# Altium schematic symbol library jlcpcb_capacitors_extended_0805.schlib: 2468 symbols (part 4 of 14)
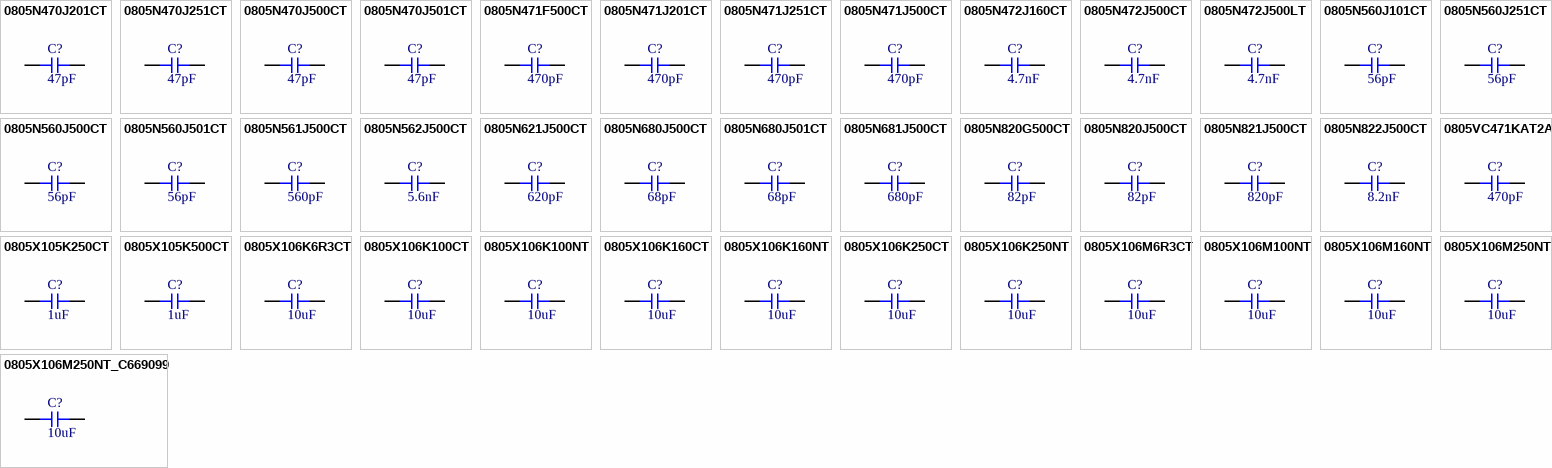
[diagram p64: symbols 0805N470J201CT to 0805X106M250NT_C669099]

## 0805N621J500CT
designator C?  Capacitance: 620pF  (hidden comment: *)
Capacitor, Ceramic (MLCC), 620pF, ±5%, 50V, NP0, ±5%, SMD 0805; Manufacturer: Walsin Tech Corp; Manufacturer Part Number: 0805N621J500CT
footprint CAP-0805 (0805 (2012M) Capacitor)
pins: 1, 2

## 0805N680J500CT
designator C?  Capacitance: 68pF  (hidden comment: *)
Capacitor, Ceramic (MLCC), 68pF, ±5%, 50V, NP0, ±5%, SMD 0805; Manufacturer: Walsin Tech Corp; Manufacturer Part Number: 0805N680J500CT
footprint CAP-0805 (0805 (2012M) Capacitor)
pins: 1, 2

## 0805N680J501CT
designator C?  Capacitance: 68pF  (hidden comment: *)
Capacitor, Ceramic (MLCC), 68pF, ±5%, 500V, NP0, ±5%, SMD 0805; Manufacturer: Walsin Tech Corp; Manufacturer Part Number: 0805N680J501CT
footprint CAP-0805 (0805 (2012M) Capacitor)
pins: 1, 2

## 0805N681J500CT
designator C?  Capacitance: 680pF  (hidden comment: *)
Capacitor, Ceramic (MLCC), 680pF, ±5%, 50V, NP0, ±5%, SMD 0805; Manufacturer: Walsin Tech Corp; Manufacturer Part Number: 0805N681J500CT
footprint CAP-0805 (0805 (2012M) Capacitor)
pins: 1, 2

## 0805N820G500CT
designator C?  Capacitance: 82pF  (hidden comment: *)
Capacitor, Ceramic (MLCC), 82pF, ±2%, 50V, NP0, ±2%, SMD 0805; Manufacturer: Walsin Tech Corp; Manufacturer Part Number: 0805N820G500CT
footprint CAP-0805 (0805 (2012M) Capacitor)
pins: 1, 2

## 0805N820J500CT
designator C?  Capacitance: 82pF  (hidden comment: *)
Capacitor, Ceramic (MLCC), 82pF, ±5%, 50V, NP0, ±5%, SMD 0805; Manufacturer: Walsin Tech Corp; Manufacturer Part Number: 0805N820J500CT
footprint CAP-0805 (0805 (2012M) Capacitor)
pins: 1, 2

## 0805N821J500CT
designator C?  Capacitance: 820pF  (hidden comment: *)
Capacitor, Ceramic (MLCC), 820pF, ±5%, 50V, NP0, ±5%, SMD 0805; Manufacturer: Walsin Tech Corp; Manufacturer Part Number: 0805N821J500CT
footprint CAP-0805 (0805 (2012M) Capacitor)
pins: 1, 2

## 0805N822J500CT
designator C?  Capacitance: 8.2nF  (hidden comment: *)
Capacitor, Ceramic (MLCC), 8.2nF, ±5%, 50V, NP0, ±5%, SMD 0805; Manufacturer: Walsin Tech Corp; Manufacturer Part Number: 0805N822J500CT
footprint CAP-0805 (0805 (2012M) Capacitor)
pins: 1, 2

## 0805VC471KAT2A
designator C?  Capacitance: 470pF  (hidden comment: *)
Capacitor, Ceramic (MLCC), 470pF, ±10%, 250V, X7R, ±10%, SMD 0805; Manufacturer: AVX; Manufacturer Part Number: 0805VC471KAT2A
footprint CAP-0805 (0805 (2012M) Capacitor)
pins: 1, 2

## 0805X105K250CT
designator C?  Capacitance: 1uF  (hidden comment: *)
Capacitor, Ceramic (MLCC), 1uF, ±10%, 25V, X5R, ±10%, SMD 0805; Manufacturer: Walsin Tech Corp; Manufacturer Part Number: 0805X105K250CT
footprint CAP-0805 (0805 (2012M) Capacitor)
pins: 1, 2

## 0805X105K500CT
designator C?  Capacitance: 1uF  (hidden comment: *)
Capacitor, Ceramic (MLCC), 1uF, ±10%, 50V, X5R, ±10%, SMD 0805; Manufacturer: Walsin Tech Corp; Manufacturer Part Number: 0805X105K500CT
footprint CAP-0805 (0805 (2012M) Capacitor)
pins: 1, 2

## 0805X106K6R3CT
designator C?  Capacitance: 10uF  (hidden comment: *)
Capacitor, Ceramic (MLCC), 10uF, ±10%, 6.3V, X5R, ±10%, SMD 0805; Manufacturer: Walsin Tech Corp; Manufacturer Part Number: 0805X106K6R3CT
footprint CAP-0805 (0805 (2012M) Capacitor)
pins: 1, 2

## 0805X106K100CT
designator C?  Capacitance: 10uF  (hidden comment: *)
Capacitor, Ceramic (MLCC), 10uF, ±10%, 10V, X5R, ±10%, SMD 0805; Manufacturer: Walsin Tech Corp; Manufacturer Part Number: 0805X106K100CT
footprint CAP-0805 (0805 (2012M) Capacitor)
pins: 1, 2

## 0805X106K100NT
designator C?  Capacitance: 10uF  (hidden comment: *)
Capacitor, Ceramic (MLCC), 10uF, ±10%, 10V, X5R, ±10%, SMD 0805; Manufacturer: FH(Guangdong Fenghua Advanced Tech); Manufacturer Part Number: 0805X106K100NT
footprint CAP-0805 (0805 (2012M) Capacitor)
pins: 1, 2

## 0805X106K160CT
designator C?  Capacitance: 10uF  (hidden comment: *)
Capacitor, Ceramic (MLCC), 10uF, ±10%, 16V, X5R, ±10%, SMD 0805; Manufacturer: Walsin Tech Corp; Manufacturer Part Number: 0805X106K160CT
footprint CAP-0805 (0805 (2012M) Capacitor)
pins: 1, 2

## 0805X106K160NT
designator C?  Capacitance: 10uF  (hidden comment: *)
Capacitor, Ceramic (MLCC), 10uF, ±10%, 16V, X5R, ±10%, SMD 0805; Manufacturer: FH(Guangdong Fenghua Advanced Tech); Manufacturer Part Number: 0805X106K160NT
footprint CAP-0805 (0805 (2012M) Capacitor)
pins: 1, 2

## 0805X106K250CT
designator C?  Capacitance: 10uF  (hidden comment: *)
Capacitor, Ceramic (MLCC), 10uF, ±10%, 25V, X5R, ±10%, SMD 0805; Manufacturer: Walsin Tech Corp; Manufacturer Part Number: 0805X106K250CT
footprint CAP-0805 (0805 (2012M) Capacitor)
pins: 1, 2

## 0805X106K250NT
designator C?  Capacitance: 10uF  (hidden comment: *)
Capacitor, Ceramic (MLCC), 10uF, ±10%, 25V, X5R, ±10%, SMD 0805; Manufacturer: FH(Guangdong Fenghua Advanced Tech); Manufacturer Part Number: 0805X106K250NT
footprint CAP-0805 (0805 (2012M) Capacitor)
pins: 1, 2

## 0805X106M6R3CT
designator C?  Capacitance: 10uF  (hidden comment: *)
Capacitor, Ceramic (MLCC), 10uF, ±20%, 6.3V, X5R, ±20%, SMD 0805; Manufacturer: Walsin Tech Corp; Manufacturer Part Number: 0805X106M6R3CT
footprint CAP-0805 (0805 (2012M) Capacitor)
pins: 1, 2

## 0805X106M100NT
designator C?  Capacitance: 10uF  (hidden comment: *)
Capacitor, Ceramic (MLCC), 10uF, ±20%, 10V, X5R, ±20%, SMD 0805; Manufacturer: FH(Guangdong Fenghua Advanced Tech); Manufacturer Part Number: 0805X106M100NT
footprint CAP-0805 (0805 (2012M) Capacitor)
pins: 1, 2

## 0805X106M160NT
designator C?  Capacitance: 10uF  (hidden comment: *)
Capacitor, Ceramic (MLCC), 10uF, ±20%, 16V, X5R, ±20%, SMD 0805; Manufacturer: FH(Guangdong Fenghua Advanced Tech); Manufacturer Part Number: 0805X106M160NT
footprint CAP-0805 (0805 (2012M) Capacitor)
pins: 1, 2

## 0805X106M250NT
designator C?  Capacitance: 10uF  (hidden comment: *)
Capacitor, Ceramic (MLCC), 10uF, ±20%, 25V, X5R, ±20%, SMD 0805; Manufacturer: FH(Guangdong Fenghua Advanced Tech); Manufacturer Part Number: 0805X106M250NT
footprint CAP-0805 (0805 (2012M) Capacitor)
pins: 1, 2

## 0805X106M250NT_C669099
designator C?  Capacitance: 10uF  (hidden comment: *)
Capacitor, Ceramic (MLCC), 10uF, ±20%, 25V, X5R, ±20%, SMD 0805; Manufacturer: FH(Guangdong Fenghua Advanced Tech); Manufacturer Part Number: 0805X106M250NT
footprint CAP-0805 (0805 (2012M) Capacitor)
pins: 1, 2

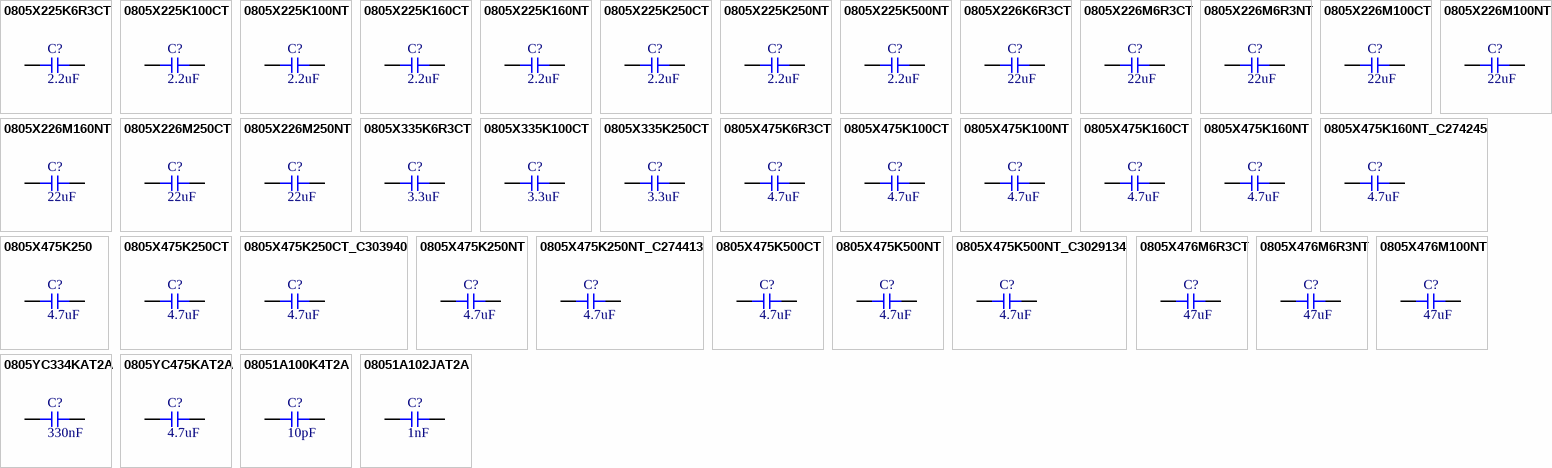
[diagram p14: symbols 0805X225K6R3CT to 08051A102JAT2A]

## 0805X225K6R3CT
designator C?  Capacitance: 2.2uF  (hidden comment: *)
Capacitor, Ceramic (MLCC), 2.2uF, ±10%, 6.3V, X5R, ±10%, SMD 0805; Manufacturer: Walsin Tech Corp; Manufacturer Part Number: 0805X225K6R3CT
footprint CAP-0805 (0805 (2012M) Capacitor)
pins: 1, 2

## 0805X225K100CT
designator C?  Capacitance: 2.2uF  (hidden comment: *)
Capacitor, Ceramic (MLCC), 2.2uF, ±10%, 10V, X5R, ±10%, SMD 0805; Manufacturer: Walsin Tech Corp; Manufacturer Part Number: 0805X225K100CT
footprint CAP-0805 (0805 (2012M) Capacitor)
pins: 1, 2

## 0805X225K100NT
designator C?  Capacitance: 2.2uF  (hidden comment: *)
Capacitor, Ceramic (MLCC), 2.2uF, ±10%, 10V, ±10%, SMD 0805; Manufacturer: FH(Guangdong Fenghua Advanced Tech); Manufacturer Part Number: 0805X225K100NT
footprint CAP-0805 (0805 (2012M) Capacitor)
pins: 1, 2

## 0805X225K160CT
designator C?  Capacitance: 2.2uF  (hidden comment: *)
Capacitor, Ceramic (MLCC), 2.2uF, ±10%, 16V, X5R, ±10%, SMD 0805; Manufacturer: Walsin Tech Corp; Manufacturer Part Number: 0805X225K160CT
footprint CAP-0805 (0805 (2012M) Capacitor)
pins: 1, 2

## 0805X225K160NT
designator C?  Capacitance: 2.2uF  (hidden comment: *)
Capacitor, Ceramic (MLCC), 2.2uF, ±10%, 16V, X5R, ±10%, SMD 0805; Manufacturer: FH(Guangdong Fenghua Advanced Tech); Manufacturer Part Number: 0805X225K160NT
footprint CAP-0805 (0805 (2012M) Capacitor)
pins: 1, 2

## 0805X225K250CT
designator C?  Capacitance: 2.2uF  (hidden comment: *)
Capacitor, Ceramic (MLCC), 2.2uF, ±10%, 25V, X5R, ±10%, SMD 0805; Manufacturer: Walsin Tech Corp; Manufacturer Part Number: 0805X225K250CT
footprint CAP-0805 (0805 (2012M) Capacitor)
pins: 1, 2

## 0805X225K250NT
designator C?  Capacitance: 2.2uF  (hidden comment: *)
Capacitor, Ceramic (MLCC), 2.2uF, ±10%, 25V, X5R, ±10%, SMD 0805; Manufacturer: FH(Guangdong Fenghua Advanced Tech); Manufacturer Part Number: 0805X225K250NT
footprint CAP-0805 (0805 (2012M) Capacitor)
pins: 1, 2

## 0805X225K500NT
designator C?  Capacitance: 2.2uF  (hidden comment: *)
Capacitor, Ceramic (MLCC), 2.2uF, ±10%, 50V, X5R, ±10%, SMD 0805; Manufacturer: FH(Guangdong Fenghua Advanced Tech); Manufacturer Part Number: 0805X225K500NT
footprint CAP-0805 (0805 (2012M) Capacitor)
pins: 1, 2

## 0805X226K6R3CT
designator C?  Capacitance: 22uF  (hidden comment: *)
Capacitor, Ceramic (MLCC), 22uF, ±10%, 6.3V, X5R, ±10%, SMD 0805; Manufacturer: Walsin Tech Corp; Manufacturer Part Number: 0805X226K6R3CT
footprint CAP-0805 (0805 (2012M) Capacitor)
pins: 1, 2

## 0805X226M6R3CT
designator C?  Capacitance: 22uF  (hidden comment: *)
Capacitor, Ceramic (MLCC), 22uF, ±20%, 6.3V, X5R, ±20%, SMD 0805; Manufacturer: Walsin Tech Corp; Manufacturer Part Number: 0805X226M6R3CT
footprint CAP-0805 (0805 (2012M) Capacitor)
pins: 1, 2

## 0805X226M6R3NT
designator C?  Capacitance: 22uF  (hidden comment: *)
Capacitor, Ceramic (MLCC), 22uF, ±20%, 6.3V, X5R, ±20%, SMD 0805; Manufacturer: FH(Guangdong Fenghua Advanced Tech); Manufacturer Part Number: 0805X226M6R3NT
footprint CAP-0805 (0805 (2012M) Capacitor)
pins: 1, 2

## 0805X226M100CT
designator C?  Capacitance: 22uF  (hidden comment: *)
Capacitor, Ceramic (MLCC), 22uF, ±20%, 10V, X5R, ±20%, SMD 0805; Manufacturer: Walsin Tech Corp; Manufacturer Part Number: 0805X226M100CT
footprint CAP-0805 (0805 (2012M) Capacitor)
pins: 1, 2

## 0805X226M100NT
designator C?  Capacitance: 22uF  (hidden comment: *)
Capacitor, Ceramic (MLCC), 22uF, ±20%, 10V, X5R, ±20%, SMD 0805; Manufacturer: FH(Guangdong Fenghua Advanced Tech); Manufacturer Part Number: 0805X226M100NT
footprint CAP-0805 (0805 (2012M) Capacitor)
pins: 1, 2

## 0805X226M160NT
designator C?  Capacitance: 22uF  (hidden comment: *)
Capacitor, Ceramic (MLCC), 22uF, ±20%, 16V, X5R, ±20%, SMD 0805; Manufacturer: FH(Guangdong Fenghua Advanced Tech); Manufacturer Part Number: 0805X226M160NT
footprint CAP-0805 (0805 (2012M) Capacitor)
pins: 1, 2

## 0805X226M250CT
designator C?  Capacitance: 22uF  (hidden comment: *)
Capacitor, Ceramic (MLCC), 22uF, ±20%, 25V, X5R, ±20%, SMD 0805; Manufacturer: Walsin Tech Corp; Manufacturer Part Number: 0805X226M250CT
footprint CAP-0805 (0805 (2012M) Capacitor)
pins: 1, 2

## 0805X226M250NT
designator C?  Capacitance: 22uF  (hidden comment: *)
Capacitor, Ceramic (MLCC), 22uF, ±20%, 25V, X5R, ±20%, SMD 0805; Manufacturer: FH(Guangdong Fenghua Advanced Tech); Manufacturer Part Number: 0805X226M250NT
footprint CAP-0805 (0805 (2012M) Capacitor)
pins: 1, 2

## 0805X335K6R3CT
designator C?  Capacitance: 3.3uF  (hidden comment: *)
Capacitor, Ceramic (MLCC), 3.3uF, ±10%, 6.3V, X5R, ±10%, SMD 0805; Manufacturer: Walsin Tech Corp; Manufacturer Part Number: 0805X335K6R3CT
footprint CAP-0805 (0805 (2012M) Capacitor)
pins: 1, 2

## 0805X335K100CT
designator C?  Capacitance: 3.3uF  (hidden comment: *)
Capacitor, Ceramic (MLCC), 3.3uF, ±10%, 10V, X5R, ±10%, SMD 0805; Manufacturer: Walsin Tech Corp; Manufacturer Part Number: 0805X335K100CT
footprint CAP-0805 (0805 (2012M) Capacitor)
pins: 1, 2

## 0805X335K250CT
designator C?  Capacitance: 3.3uF  (hidden comment: *)
Capacitor, Ceramic (MLCC), 3.3uF, ±10%, 25V, X5R, ±10%, SMD 0805; Manufacturer: Walsin Tech Corp; Manufacturer Part Number: 0805X335K250CT
footprint CAP-0805 (0805 (2012M) Capacitor)
pins: 1, 2

## 0805X475K6R3CT
designator C?  Capacitance: 4.7uF  (hidden comment: *)
Capacitor, Ceramic (MLCC), 4.7uF, ±10%, 6.3V, X5R, ±10%, SMD 0805; Manufacturer: Walsin Tech Corp; Manufacturer Part Number: 0805X475K6R3CT
footprint CAP-0805 (0805 (2012M) Capacitor)
pins: 1, 2

## 0805X475K100CT
designator C?  Capacitance: 4.7uF  (hidden comment: *)
Capacitor, Ceramic (MLCC), 4.7uF, ±10%, 10V, X5R, ±10%, SMD 0805; Manufacturer: Walsin Tech Corp; Manufacturer Part Number: 0805X475K100CT
footprint CAP-0805 (0805 (2012M) Capacitor)
pins: 1, 2

## 0805X475K100NT
designator C?  Capacitance: 4.7uF  (hidden comment: *)
Capacitor, Ceramic (MLCC), 4.7uF, ±10%, 10V, ±10%, SMD 0805; Manufacturer: FH(Guangdong Fenghua Advanced Tech); Manufacturer Part Number: 0805X475K100NT
footprint CAP-0805 (0805 (2012M) Capacitor)
pins: 1, 2

## 0805X475K160CT
designator C?  Capacitance: 4.7uF  (hidden comment: *)
Capacitor, Ceramic (MLCC), 4.7uF, ±10%, 16V, X5R, ±10%, SMD 0805; Manufacturer: Walsin Tech Corp; Manufacturer Part Number: 0805X475K160CT
footprint CAP-0805 (0805 (2012M) Capacitor)
pins: 1, 2

## 0805X475K160NT
designator C?  Capacitance: 4.7uF  (hidden comment: *)
Capacitor, Ceramic (MLCC), 4.7uF, ±10%, 16V, X5R, ±10%, SMD 0805; Manufacturer: FH(Guangdong Fenghua Advanced Tech); Manufacturer Part Number: 0805X475K160NT
footprint CAP-0805 (0805 (2012M) Capacitor)
pins: 1, 2

## 0805X475K160NT_C274245
designator C?  Capacitance: 4.7uF  (hidden comment: *)
Capacitor, Ceramic (MLCC), 4.7uF, ±10%, 16V, X5R, ±10%, SMD 0805; Manufacturer: FH(Guangdong Fenghua Advanced Tech); Manufacturer Part Number: 0805X475K160NT
footprint CAP-0805 (0805 (2012M) Capacitor)
pins: 1, 2

## 0805X475K250
designator C?  Capacitance: 4.7uF  (hidden comment: *)
Capacitor, Ceramic (MLCC), 4.7uF, ±10%, 25V, X5R, ±10%, SMD 0805; Manufacturer: Walsin Tech Corp; Manufacturer Part Number: 0805X475K250
footprint CAP-0805 (0805 (2012M) Capacitor)
pins: 1, 2

## 0805X475K250CT
designator C?  Capacitance: 4.7uF  (hidden comment: *)
Capacitor, Ceramic (MLCC), 4.7uF, ±10%, 25V, X5R, ±10%, SMD 0805; Manufacturer: Guangdong TOPAZ Elec Tech; Manufacturer Part Number: 0805X475K250CT
footprint CAP-0805 (0805 (2012M) Capacitor)
pins: 1, 2

## 0805X475K250CT_C303940
designator C?  Capacitance: 4.7uF  (hidden comment: *)
Capacitor, Ceramic (MLCC), 4.7uF, ±10%, 25V, X5R, ±10%, SMD 0805; Manufacturer: Walsin Tech Corp; Manufacturer Part Number: 0805X475K250CT
footprint CAP-0805 (0805 (2012M) Capacitor)
pins: 1, 2

## 0805X475K250NT
designator C?  Capacitance: 4.7uF  (hidden comment: *)
Capacitor, Ceramic (MLCC), 4.7uF, ±10%, 25V, X5R, ±10%, SMD 0805; Manufacturer: FH(Guangdong Fenghua Advanced Tech); Manufacturer Part Number: 0805X475K250NT
footprint CAP-0805 (0805 (2012M) Capacitor)
pins: 1, 2

## 0805X475K250NT_C274413
designator C?  Capacitance: 4.7uF  (hidden comment: *)
Capacitor, Ceramic (MLCC), 4.7uF, ±10%, 25V, X5R, ±10%, SMD 0805; Manufacturer: FH(Guangdong Fenghua Advanced Tech); Manufacturer Part Number: 0805X475K250NT
footprint CAP-0805 (0805 (2012M) Capacitor)
pins: 1, 2

## 0805X475K500CT
designator C?  Capacitance: 4.7uF  (hidden comment: *)
Capacitor, Ceramic (MLCC), 4.7uF, ±10%, 50V, X5R, ±10%, SMD 0805; Manufacturer: Walsin Tech Corp; Manufacturer Part Number: 0805X475K500CT
footprint CAP-0805 (0805 (2012M) Capacitor)
pins: 1, 2

## 0805X475K500NT
designator C?  Capacitance: 4.7uF  (hidden comment: *)
Capacitor, Ceramic (MLCC), 4.7uF, ±10%, 50V, X5R, ±10%, SMD 0805; Manufacturer: FH (Guangdong Fenghua Advanced Tech); Manufacturer Part Number: 0805X475K500NT
footprint CAP-0805 (0805 (2012M) Capacitor)
pins: 1, 2

## 0805X475K500NT_C3029134
designator C?  Capacitance: 4.7uF  (hidden comment: *)
Capacitor, Ceramic (MLCC), 4.7uF, ±10%, 50V, X5R, ±10%, SMD 0805; Manufacturer: FH (Guangdong Fenghua Advanced Tech); Manufacturer Part Number: 0805X475K500NT
footprint CAP-0805 (0805 (2012M) Capacitor)
pins: 1, 2

## 0805X476M6R3CT
designator C?  Capacitance: 47uF  (hidden comment: *)
Capacitor, Ceramic (MLCC), 47uF, ±20%, 6.3V, X5R, ±20%, SMD 0805; Manufacturer: Walsin Tech Corp; Manufacturer Part Number: 0805X476M6R3CT
footprint CAP-0805 (0805 (2012M) Capacitor)
pins: 1, 2

## 0805X476M6R3NT
designator C?  Capacitance: 47uF  (hidden comment: *)
Capacitor, Ceramic (MLCC), 47uF, ±20%, 6.3V, X5R, ±20%, SMD 0805; Manufacturer: FH(Guangdong Fenghua Advanced Tech); Manufacturer Part Number: 0805X476M6R3NT
footprint CAP-0805 (0805 (2012M) Capacitor)
pins: 1, 2

## 0805X476M100NT
designator C?  Capacitance: 47uF  (hidden comment: *)
Capacitor, Ceramic (MLCC), 47uF, ±20%, 10V, X5R, ±20%, SMD 0805; Manufacturer: FH(Guangdong Fenghua Advanced Tech); Manufacturer Part Number: 0805X476M100NT
footprint CAP-0805 (0805 (2012M) Capacitor)
pins: 1, 2

## 0805YC334KAT2A
designator C?  Capacitance: 330nF  (hidden comment: *)
Capacitor, Ceramic (MLCC), 330nF, ±10%, 16V, X7R, ±10%, SMD 0805; Manufacturer: AVX; Manufacturer Part Number: 0805YC334KAT2A
footprint CAP-0805 (0805 (2012M) Capacitor)
pins: 1, 2

## 0805YC475KAT2A
designator C?  Capacitance: 4.7uF  (hidden comment: *)
Capacitor, Ceramic (MLCC), 4.7uF, ±10%, 16V, X7R, ±10%, SMD 0805; Manufacturer: AVX; Manufacturer Part Number: 0805YC475KAT2A
footprint CAP-0805 (0805 (2012M) Capacitor)
pins: 1, 2

## 08051A100K4T2A
designator C?  Capacitance: 10pF  (hidden comment: *)
Capacitor, Ceramic (MLCC), 10pF, ±10%, 100V, C0G, ±10%, SMD 0805; Manufacturer: AVX; Manufacturer Part Number: 08051A100K4T2A
footprint CAP-0805 (0805 (2012M) Capacitor)
pins: 1, 2

## 08051A102JAT2A
designator C?  Capacitance: 1nF  (hidden comment: *)
Capacitor, Ceramic (MLCC), 1nF, ±5%, 100V, C0G, ±5%, SMD 0805; Manufacturer: AVX; Manufacturer Part Number: 08051A102JAT2A
footprint CAP-0805 (0805 (2012M) Capacitor)
pins: 1, 2

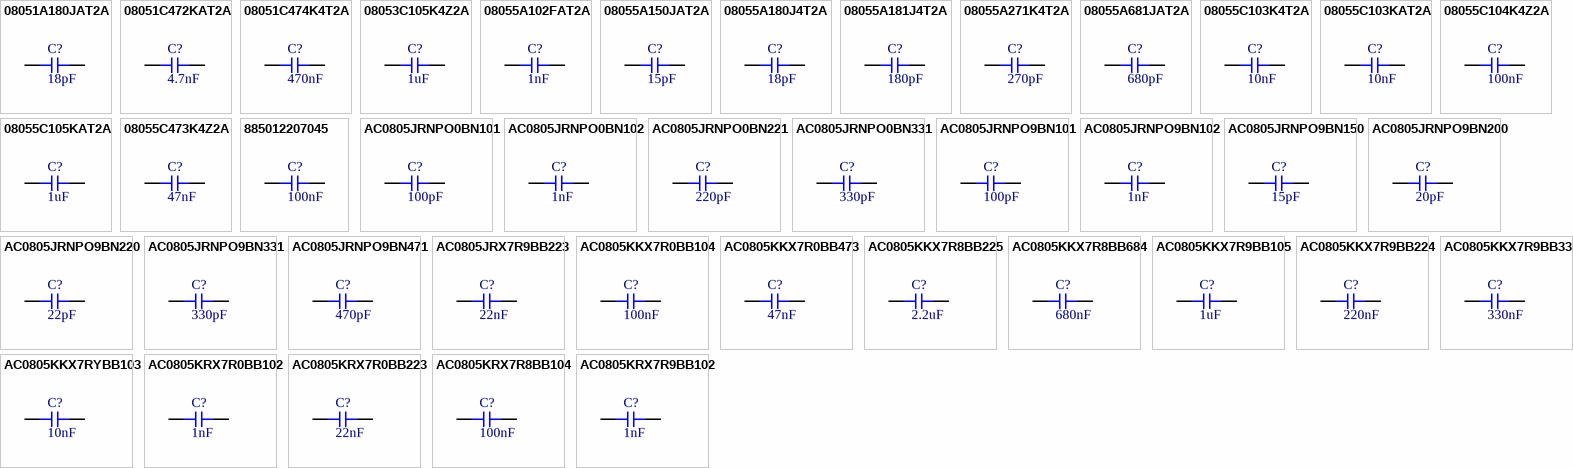
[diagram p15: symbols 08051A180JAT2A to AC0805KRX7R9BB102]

## 08051A180JAT2A
designator C?  Capacitance: 18pF  (hidden comment: *)
Capacitor, Ceramic (MLCC), 18pF, ±5%, 100V, C0G, ±5%, SMD 0805; Manufacturer: AVX; Manufacturer Part Number: 08051A180JAT2A
footprint CAP-0805 (0805 (2012M) Capacitor)
pins: 1, 2

## 08051C472KAT2A
designator C?  Capacitance: 4.7nF  (hidden comment: *)
Capacitor, Ceramic (MLCC), 4.7nF, ±10%, 100V, X7R, ±10%, SMD 0805; Manufacturer: AVX; Manufacturer Part Number: 08051C472KAT2A
footprint CAP-0805 (0805 (2012M) Capacitor)
pins: 1, 2

## 08051C474K4T2A
designator C?  Capacitance: 470nF  (hidden comment: *)
Capacitor, Ceramic (MLCC), 470nF, ±10%, 100V, X7R, ±10%, SMD 0805; Manufacturer: AVX; Manufacturer Part Number: 08051C474K4T2A
footprint CAP-0805 (0805 (2012M) Capacitor)
pins: 1, 2

## 08053C105K4Z2A
designator C?  Capacitance: 1uF  (hidden comment: *)
Capacitor, Ceramic (MLCC), 1uF, ±10%, 25V, X7R, ±10%, SMD 0805; Manufacturer: AVX; Manufacturer Part Number: 08053C105K4Z2A
footprint CAP-0805 (0805 (2012M) Capacitor)
pins: 1, 2

## 08055A102FAT2A
designator C?  Capacitance: 1nF  (hidden comment: *)
Capacitor, Ceramic (MLCC), 1nF, ±1%, 50V, C0G, ±1%, SMD 0805; Manufacturer: AVX; Manufacturer Part Number: 08055A102FAT2A
footprint CAP-0805 (0805 (2012M) Capacitor)
pins: 1, 2

## 08055A150JAT2A
designator C?  Capacitance: 15pF  (hidden comment: *)
Capacitor, Ceramic (MLCC), 15pF, ±5%, 50V, C0G, ±5%, SMD 0805; Manufacturer: AVX; Manufacturer Part Number: 08055A150JAT2A
footprint CAP-0805 (0805 (2012M) Capacitor)
pins: 1, 2

## 08055A180J4T2A
designator C?  Capacitance: 18pF  (hidden comment: *)
Capacitor, Ceramic (MLCC), 18pF, ±5%, 50V, C0G, ±5%, SMD 0805; Manufacturer: AVX; Manufacturer Part Number: 08055A180J4T2A
footprint CAP-0805 (0805 (2012M) Capacitor)
pins: 1, 2

## 08055A181J4T2A
designator C?  Capacitance: 180pF  (hidden comment: *)
Capacitor, Ceramic (MLCC), 180pF, ±5%, 50V, C0G, ±5%, SMD 0805; Manufacturer: AVX; Manufacturer Part Number: 08055A181J4T2A
footprint CAP-0805 (0805 (2012M) Capacitor)
pins: 1, 2

## 08055A271K4T2A
designator C?  Capacitance: 270pF  (hidden comment: *)
Capacitor, Ceramic (MLCC), 270pF, ±10%, 50V, C0G, ±10%, SMD 0805; Manufacturer: AVX; Manufacturer Part Number: 08055A271K4T2A
footprint CAP-0805 (0805 (2012M) Capacitor)
pins: 1, 2

## 08055A681JAT2A
designator C?  Capacitance: 680pF  (hidden comment: *)
Capacitor, Ceramic (MLCC), 680pF, ±5%, 50V, C0G, ±5%, SMD 0805; Manufacturer: AVX; Manufacturer Part Number: 08055A681JAT2A
footprint CAP-0805 (0805 (2012M) Capacitor)
pins: 1, 2

## 08055C103K4T2A
designator C?  Capacitance: 10nF  (hidden comment: *)
Capacitor, Ceramic (MLCC), 10nF, ±10%, 50V, X7R, ±10%, SMD 0805; Manufacturer: AVX; Manufacturer Part Number: 08055C103K4T2A
footprint CAP-0805 (0805 (2012M) Capacitor)
pins: 1, 2

## 08055C103KAT2A
designator C?  Capacitance: 10nF  (hidden comment: *)
Capacitor, Ceramic (MLCC), 10nF, ±10%, 50V, X7R, ±10%, SMD 0805; Manufacturer: AVX; Manufacturer Part Number: 08055C103KAT2A
footprint CAP-0805 (0805 (2012M) Capacitor)
pins: 1, 2

## 08055C104K4Z2A
designator C?  Capacitance: 100nF  (hidden comment: *)
Capacitor, Ceramic (MLCC), 100nF, ±10%, 50V, X7R, ±10%, SMD 0805; Manufacturer: Kyocera AVX; Manufacturer Part Number: 08055C104K4Z2A
footprint CAP-0805 (0805 (2012M) Capacitor)
pins: 1, 2

## 08055C105KAT2A
designator C?  Capacitance: 1uF  (hidden comment: *)
Capacitor, Ceramic (MLCC), 1uF, ±10%, 50V, X7R, ±10%, SMD 0805; Manufacturer: AVX; Manufacturer Part Number: 08055C105KAT2A
footprint CAP-0805 (0805 (2012M) Capacitor)
pins: 1, 2

## 08055C473K4Z2A
designator C?  Capacitance: 47nF  (hidden comment: *)
Capacitor, Ceramic (MLCC), 47nF, ±10%, 50V, X7R, ±10%, SMD 0805; Manufacturer: AVX; Manufacturer Part Number: 08055C473K4Z2A
footprint CAP-0805 (0805 (2012M) Capacitor)
pins: 1, 2

## 885012207045
designator C?  Capacitance: 100nF  (hidden comment: *)
Capacitor, Ceramic (MLCC), 100nF, ±10%, 16V, ±10%, SMD 0805; Manufacturer: Wurth Elektronik; Manufacturer Part Number: 885012207045
footprint CAP-0805 (0805 (2012M) Capacitor)
pins: 1, 2

## AC0805JRNPO0BN101
designator C?  Capacitance: 100pF  (hidden comment: *)
Capacitor, Ceramic (MLCC), 100pF, ±5%, 100V, ±5%, SMD 0805; Manufacturer: YAGEO; Manufacturer Part Number: AC0805JRNPO0BN101
footprint CAP-0805 (0805 (2012M) Capacitor)
pins: 1, 2

## AC0805JRNPO0BN102
designator C?  Capacitance: 1nF  (hidden comment: *)
Capacitor, Ceramic (MLCC), 1nF, ±5%, 100V, NP0, ±5%, SMD 0805; Manufacturer: YAGEO; Manufacturer Part Number: AC0805JRNPO0BN102
footprint CAP-0805 (0805 (2012M) Capacitor)
pins: 1, 2

## AC0805JRNPO0BN221
designator C?  Capacitance: 220pF  (hidden comment: *)
Capacitor, Ceramic (MLCC), 220pF, ±5%, 100V, NP0, ±5%, SMD 0805; Manufacturer: YAGEO; Manufacturer Part Number: AC0805JRNPO0BN221
footprint CAP-0805 (0805 (2012M) Capacitor)
pins: 1, 2

## AC0805JRNPO0BN331
designator C?  Capacitance: 330pF  (hidden comment: *)
Capacitor, Ceramic (MLCC), 330pF, ±5%, 100V, NP0, ±5%, SMD 0805; Manufacturer: YAGEO; Manufacturer Part Number: AC0805JRNPO0BN331
footprint CAP-0805 (0805 (2012M) Capacitor)
pins: 1, 2

## AC0805JRNPO9BN101
designator C?  Capacitance: 100pF  (hidden comment: *)
Capacitor, Ceramic (MLCC), 100pF, ±5%, 50V, NP0, ±5%, SMD 0805; Manufacturer: YAGEO; Manufacturer Part Number: AC0805JRNPO9BN101
footprint CAP-0805 (0805 (2012M) Capacitor)
pins: 1, 2

## AC0805JRNPO9BN102
designator C?  Capacitance: 1nF  (hidden comment: *)
Capacitor, Ceramic (MLCC), 1nF, ±5%, 50V, ±5%, SMD 0805; Manufacturer: YAGEO; Manufacturer Part Number: AC0805JRNPO9BN102
footprint CAP-0805 (0805 (2012M) Capacitor)
pins: 1, 2

## AC0805JRNPO9BN150
designator C?  Capacitance: 15pF  (hidden comment: *)
Capacitor, Ceramic (MLCC), 15pF, ±5%, 50V, NP0, ±5%, SMD 0805; Manufacturer: YAGEO; Manufacturer Part Number: AC0805JRNPO9BN150
footprint CAP-0805 (0805 (2012M) Capacitor)
pins: 1, 2

## AC0805JRNPO9BN200
designator C?  Capacitance: 20pF  (hidden comment: *)
Capacitor, Ceramic (MLCC), 20pF, ±5%, 50V, NP0, ±5%, SMD 0805; Manufacturer: YAGEO; Manufacturer Part Number: AC0805JRNPO9BN200
footprint CAP-0805 (0805 (2012M) Capacitor)
pins: 1, 2

## AC0805JRNPO9BN220
designator C?  Capacitance: 22pF  (hidden comment: *)
Capacitor, Ceramic (MLCC), 22pF, ±5%, 50V, NP0, ±5%, SMD 0805; Manufacturer: YAGEO; Manufacturer Part Number: AC0805JRNPO9BN220
footprint CAP-0805 (0805 (2012M) Capacitor)
pins: 1, 2

## AC0805JRNPO9BN331
designator C?  Capacitance: 330pF  (hidden comment: *)
Capacitor, Ceramic (MLCC), 330pF, ±5%, 50V, NP0, ±5%, SMD 0805; Manufacturer: YAGEO; Manufacturer Part Number: AC0805JRNPO9BN331
footprint CAP-0805 (0805 (2012M) Capacitor)
pins: 1, 2

## AC0805JRNPO9BN471
designator C?  Capacitance: 470pF  (hidden comment: *)
Capacitor, Ceramic (MLCC), 470pF, ±5%, 50V, NP0, ±5%, SMD 0805; Manufacturer: YAGEO; Manufacturer Part Number: AC0805JRNPO9BN471
footprint CAP-0805 (0805 (2012M) Capacitor)
pins: 1, 2

## AC0805JRX7R9BB223
designator C?  Capacitance: 22nF  (hidden comment: *)
Capacitor, Ceramic (MLCC), 22nF, ±5%, 50V, X7R, ±5%, SMD 0805; Manufacturer: YAGEO; Manufacturer Part Number: AC0805JRX7R9BB223
footprint CAP-0805 (0805 (2012M) Capacitor)
pins: 1, 2

## AC0805KKX7R0BB104
designator C?  Capacitance: 100nF  (hidden comment: *)
Capacitor, Ceramic (MLCC), 100nF, ±10%, 100V, X7R, ±10%, SMD 0805; Manufacturer: YAGEO; Manufacturer Part Number: AC0805KKX7R0BB104
footprint CAP-0805 (0805 (2012M) Capacitor)
pins: 1, 2

## AC0805KKX7R0BB473
designator C?  Capacitance: 47nF  (hidden comment: *)
Capacitor, Ceramic (MLCC), 47nF, ±10%, 100V, X7R, ±10%, SMD 0805; Manufacturer: YAGEO; Manufacturer Part Number: AC0805KKX7R0BB473
footprint CAP-0805 (0805 (2012M) Capacitor)
pins: 1, 2

## AC0805KKX7R8BB225
designator C?  Capacitance: 2.2uF  (hidden comment: *)
Capacitor, Ceramic (MLCC), 2.2uF, ±10%, 25V, X7R, ±10%, SMD 0805; Manufacturer: YAGEO; Manufacturer Part Number: AC0805KKX7R8BB225
footprint CAP-0805 (0805 (2012M) Capacitor)
pins: 1, 2

## AC0805KKX7R8BB684
designator C?  Capacitance: 680nF  (hidden comment: *)
Capacitor, Ceramic (MLCC), 680nF, ±10%, 25V, X7R, ±10%, SMD 0805; Manufacturer: YAGEO; Manufacturer Part Number: AC0805KKX7R8BB684
footprint CAP-0805 (0805 (2012M) Capacitor)
pins: 1, 2

## AC0805KKX7R9BB105
designator C?  Capacitance: 1uF  (hidden comment: *)
Capacitor, Ceramic (MLCC), 1uF, ±10%, 50V, X7R, ±10%, SMD 0805; Manufacturer: YAGEO; Manufacturer Part Number: AC0805KKX7R9BB105
footprint CAP-0805 (0805 (2012M) Capacitor)
pins: 1, 2

## AC0805KKX7R9BB224
designator C?  Capacitance: 220nF  (hidden comment: *)
Capacitor, Ceramic (MLCC), 220nF, ±10%, 50V, X7R, ±10%, SMD 0805; Manufacturer: YAGEO; Manufacturer Part Number: AC0805KKX7R9BB224
footprint CAP-0805 (0805 (2012M) Capacitor)
pins: 1, 2

## AC0805KKX7R9BB334
designator C?  Capacitance: 330nF  (hidden comment: *)
Capacitor, Ceramic (MLCC), 330nF, ±10%, 50V, X7R, ±10%, SMD 0805; Manufacturer: YAGEO; Manufacturer Part Number: AC0805KKX7R9BB334
footprint CAP-0805 (0805 (2012M) Capacitor)
pins: 1, 2

## AC0805KKX7RYBB103
designator C?  Capacitance: 10nF  (hidden comment: *)
Capacitor, Ceramic (MLCC), 10nF, ±10%, 250V, X7R, ±10%, SMD 0805; Manufacturer: YAGEO; Manufacturer Part Number: AC0805KKX7RYBB103
footprint CAP-0805 (0805 (2012M) Capacitor)
pins: 1, 2

## AC0805KRX7R0BB102
designator C?  Capacitance: 1nF  (hidden comment: *)
Capacitor, Ceramic (MLCC), 1nF, ±10%, 100V, X7R, ±10%, SMD 0805; Manufacturer: YAGEO; Manufacturer Part Number: AC0805KRX7R0BB102
footprint CAP-0805 (0805 (2012M) Capacitor)
pins: 1, 2

## AC0805KRX7R0BB223
designator C?  Capacitance: 22nF  (hidden comment: *)
Capacitor, Ceramic (MLCC), 22nF, ±10%, 100V, X7R, ±10%, SMD 0805; Manufacturer: YAGEO; Manufacturer Part Number: AC0805KRX7R0BB223
footprint CAP-0805 (0805 (2012M) Capacitor)
pins: 1, 2

## AC0805KRX7R8BB104
designator C?  Capacitance: 100nF  (hidden comment: *)
Capacitor, Ceramic (MLCC), 100nF, ±10%, 25V, X7R, ±10%, SMD 0805; Manufacturer: YAGEO; Manufacturer Part Number: AC0805KRX7R8BB104
footprint CAP-0805 (0805 (2012M) Capacitor)
pins: 1, 2

## AC0805KRX7R9BB102
designator C?  Capacitance: 1nF  (hidden comment: *)
Capacitor, Ceramic (MLCC), 1nF, ±10%, 50V, X7R, ±10%, SMD 0805; Manufacturer: YAGEO; Manufacturer Part Number: AC0805KRX7R9BB102
footprint CAP-0805 (0805 (2012M) Capacitor)
pins: 1, 2

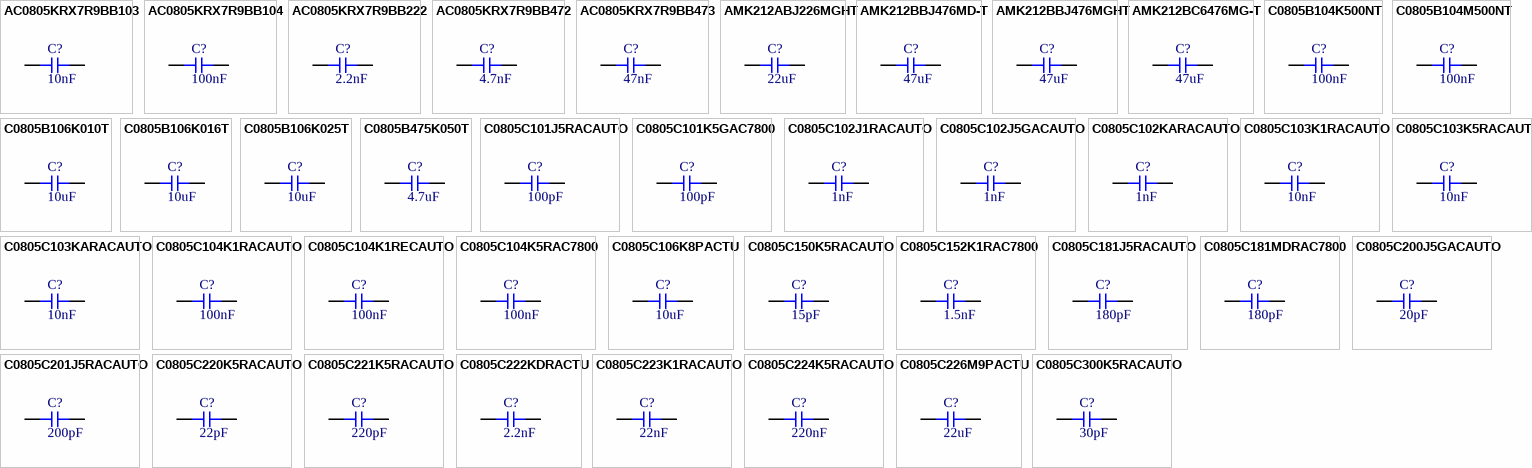
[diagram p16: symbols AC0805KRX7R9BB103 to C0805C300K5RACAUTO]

## AC0805KRX7R9BB103
designator C?  Capacitance: 10nF  (hidden comment: *)
Capacitor, Ceramic (MLCC), 10nF, ±10%, 50V, X7R, ±10%, SMD 0805; Manufacturer: YAGEO; Manufacturer Part Number: AC0805KRX7R9BB103
footprint CAP-0805 (0805 (2012M) Capacitor)
pins: 1, 2

## AC0805KRX7R9BB104
designator C?  Capacitance: 100nF  (hidden comment: *)
Capacitor, Ceramic (MLCC), 100nF, ±10%, 50V, X7R, ±10%, SMD 0805; Manufacturer: YAGEO; Manufacturer Part Number: AC0805KRX7R9BB104
footprint CAP-0805 (0805 (2012M) Capacitor)
pins: 1, 2

## AC0805KRX7R9BB222
designator C?  Capacitance: 2.2nF  (hidden comment: *)
Capacitor, Ceramic (MLCC), 2.2nF, ±10%, 50V, X7R, ±10%, SMD 0805; Manufacturer: YAGEO; Manufacturer Part Number: AC0805KRX7R9BB222
footprint CAP-0805 (0805 (2012M) Capacitor)
pins: 1, 2

## AC0805KRX7R9BB472
designator C?  Capacitance: 4.7nF  (hidden comment: *)
Capacitor, Ceramic (MLCC), 4.7nF, ±10%, 50V, X7R, ±10%, SMD 0805; Manufacturer: YAGEO; Manufacturer Part Number: AC0805KRX7R9BB472
footprint CAP-0805 (0805 (2012M) Capacitor)
pins: 1, 2

## AC0805KRX7R9BB473
designator C?  Capacitance: 47nF  (hidden comment: *)
Capacitor, Ceramic (MLCC), 47nF, ±10%, 50V, X7R, ±10%, SMD 0805; Manufacturer: YAGEO; Manufacturer Part Number: AC0805KRX7R9BB473
footprint CAP-0805 (0805 (2012M) Capacitor)
pins: 1, 2

## AMK212ABJ226MGHT
designator C?  Capacitance: 22uF  (hidden comment: *)
Capacitor, Ceramic (MLCC), 22uF, ±20%, 4V, ±20%, SMD 0805; Manufacturer: Taiyo Yuden; Manufacturer Part Number: AMK212ABJ226MGHT
footprint CAP-0805 (0805 (2012M) Capacitor)
pins: 1, 2

## AMK212BBJ476MD-T
designator C?  Capacitance: 47uF  (hidden comment: *)
Capacitor, Ceramic (MLCC), 47uF, ±20%, 4V, X5R, ±20%, SMD 0805; Manufacturer: Taiyo Yuden; Manufacturer Part Number: AMK212BBJ476MD-T
footprint CAP-0805 (0805 (2012M) Capacitor)
pins: 1, 2

## AMK212BBJ476MGHT
designator C?  Capacitance: 47uF  (hidden comment: *)
Capacitor, Ceramic (MLCC), 47uF, ±20%, 4V, X5R, ±20%, SMD 0805; Manufacturer: Taiyo Yuden; Manufacturer Part Number: AMK212BBJ476MGHT
footprint CAP-0805 (0805 (2012M) Capacitor)
pins: 1, 2

## AMK212BC6476MG-T
designator C?  Capacitance: 47uF  (hidden comment: *)
Capacitor, Ceramic (MLCC), 47uF, ±20%, 4V, ±20%, SMD 0805; Manufacturer: Taiyo Yuden; Manufacturer Part Number: AMK212BC6476MG-T
footprint CAP-0805 (0805 (2012M) Capacitor)
pins: 1, 2

## C0805B104K500NT
designator C?  Capacitance: 100nF  (hidden comment: *)
Capacitor, Ceramic (MLCC), 100nF, ±10%, 50V, X7R, ±10%, SMD 0805; Manufacturer: TORCH; Manufacturer Part Number: C0805B104K500NT
footprint CAP-0805 (0805 (2012M) Capacitor)
pins: 1, 2

## C0805B104M500NT
designator C?  Capacitance: 100nF  (hidden comment: *)
Capacitor, Ceramic (MLCC), 100nF, ±20%, 50V, X7R, ±20%, SMD 0805; Manufacturer: TORCH; Manufacturer Part Number: C0805B104M500NT
footprint CAP-0805 (0805 (2012M) Capacitor)
pins: 1, 2

## C0805B106K010T
designator C?  Capacitance: 10uF  (hidden comment: *)
Capacitor, Ceramic (MLCC), 10uF, ±10%, 10V, X5R, ±10%, SMD 0805; Manufacturer: IHHEC(HOLY STONE ENTERPRISE CO., LTD); Manufacturer Part Number: C0805B106K010T
footprint CAP-0805 (0805 (2012M) Capacitor)
pins: 1, 2

## C0805B106K016T
designator C?  Capacitance: 10uF  (hidden comment: *)
Capacitor, Ceramic (MLCC), 10uF, ±10%, 16V, X5R, ±10%, SMD 0805; Manufacturer: IHHEC(HOLY STONE ENTERPRISE CO., LTD); Manufacturer Part Number: C0805B106K016T
footprint CAP-0805 (0805 (2012M) Capacitor)
pins: 1, 2

## C0805B106K025T
designator C?  Capacitance: 10uF  (hidden comment: *)
Capacitor, Ceramic (MLCC), 10uF, ±10%, 25V, X5R, ±10%, SMD 0805; Manufacturer: IHHEC(HOLY STONE ENTERPRISE CO., LTD); Manufacturer Part Number: C0805B106K025T
footprint CAP-0805 (0805 (2012M) Capacitor)
pins: 1, 2

## C0805B475K050T
designator C?  Capacitance: 4.7uF  (hidden comment: *)
Capacitor, Ceramic (MLCC), 4.7uF, ±10%, 50V, X5R, ±10%, SMD 0805; Manufacturer: IHHEC(HOLY STONE ENTERPRISE CO., LTD); Manufacturer Part Number: C0805B475K050T
footprint CAP-0805 (0805 (2012M) Capacitor)
pins: 1, 2

## C0805C101J5RACAUTO
designator C?  Capacitance: 100pF  (hidden comment: *)
Capacitor, Ceramic (MLCC), 100pF, ±5%, 50V, X7R, ±5%, SMD 0805; Manufacturer: KEMET; Manufacturer Part Number: C0805C101J5RACAUTO
footprint CAP-0805 (0805 (2012M) Capacitor)
pins: 1, 2

## C0805C101K5GAC7800
designator C?  Capacitance: 100pF  (hidden comment: *)
Capacitor, Ceramic (MLCC), 100pF, ±10%, 50V, C0G, ±10%, SMD 0805; Manufacturer: KEMET; Manufacturer Part Number: C0805C101K5GAC7800
footprint CAP-0805 (0805 (2012M) Capacitor)
pins: 1, 2

## C0805C102J1RACAUTO
designator C?  Capacitance: 1nF  (hidden comment: *)
Capacitor, Ceramic (MLCC), 1nF, ±5%, 100V, X7R, ±5%, SMD 0805; Manufacturer: KEMET; Manufacturer Part Number: C0805C102J1RACAUTO
footprint CAP-0805 (0805 (2012M) Capacitor)
pins: 1, 2

## C0805C102J5GACAUTO
designator C?  Capacitance: 1nF  (hidden comment: *)
Capacitor, Ceramic (MLCC), 1nF, ±5%, 50V, C0G, ±5%, SMD 0805; Manufacturer: KEMET; Manufacturer Part Number: C0805C102J5GACAUTO
footprint CAP-0805 (0805 (2012M) Capacitor)
pins: 1, 2

## C0805C102KARACAUTO
designator C?  Capacitance: 1nF  (hidden comment: *)
Capacitor, Ceramic (MLCC), 1nF, ±10%, 250V, X7R, ±10%, SMD 0805; Manufacturer: KEMET; Manufacturer Part Number: C0805C102KARACAUTO
footprint CAP-0805 (0805 (2012M) Capacitor)
pins: 1, 2

## C0805C103K1RACAUTO
designator C?  Capacitance: 10nF  (hidden comment: *)
Capacitor, Ceramic (MLCC), 10nF, ±10%, 100V, X7R, ±10%, SMD 0805; Manufacturer: KEMET; Manufacturer Part Number: C0805C103K1RACAUTO
footprint CAP-0805 (0805 (2012M) Capacitor)
pins: 1, 2

## C0805C103K5RACAUTO
designator C?  Capacitance: 10nF  (hidden comment: *)
Capacitor, Ceramic (MLCC), 10nF, ±10%, 50V, X7R, ±10%, SMD 0805; Manufacturer: KEMET; Manufacturer Part Number: C0805C103K5RACAUTO
footprint CAP-0805 (0805 (2012M) Capacitor)
pins: 1, 2

## C0805C103KARACAUTO
designator C?  Capacitance: 10nF  (hidden comment: *)
Capacitor, Ceramic (MLCC), 10nF, ±10%, 250V, X7R, ±10%, SMD 0805; Manufacturer: KEMET; Manufacturer Part Number: C0805C103KARACAUTO
footprint CAP-0805 (0805 (2012M) Capacitor)
pins: 1, 2

## C0805C104K1RACAUTO
designator C?  Capacitance: 100nF  (hidden comment: *)
Capacitor, Ceramic (MLCC), 100nF, ±10%, 100V, X7R, ±10%, SMD 0805; Manufacturer: KEMET; Manufacturer Part Number: C0805C104K1RACAUTO
footprint CAP-0805 (0805 (2012M) Capacitor)
pins: 1, 2

## C0805C104K1RECAUTO
designator C?  Capacitance: 100nF  (hidden comment: *)
Capacitor, Ceramic (MLCC), 100nF, ±10%, 100V, X7R, ±10%, SMD 0805; Manufacturer: KEMET; Manufacturer Part Number: C0805C104K1RECAUTO
footprint CAP-0805 (0805 (2012M) Capacitor)
pins: 1, 2

## C0805C104K5RAC7800
designator C?  Capacitance: 100nF  (hidden comment: *)
Capacitor, Ceramic (MLCC), 100nF, ±10%, 50V, X7R, ±10%, SMD 0805; Manufacturer: KEMET; Manufacturer Part Number: C0805C104K5RAC7800
footprint CAP-0805 (0805 (2012M) Capacitor)
pins: 1, 2

## C0805C106K8PACTU
designator C?  Capacitance: 10uF  (hidden comment: *)
Capacitor, Ceramic (MLCC), 10uF, ±10%, 10V, X5R, ±10%, SMD 0805; Manufacturer: KEMET; Manufacturer Part Number: C0805C106K8PACTU
footprint CAP-0805 (0805 (2012M) Capacitor)
pins: 1, 2

## C0805C150K5RACAUTO
designator C?  Capacitance: 15pF  (hidden comment: *)
Capacitor, Ceramic (MLCC), 15pF, ±10%, 50V, X7R, ±10%, SMD 0805; Manufacturer: KEMET; Manufacturer Part Number: C0805C150K5RACAUTO
footprint CAP-0805 (0805 (2012M) Capacitor)
pins: 1, 2

## C0805C152K1RAC7800
designator C?  Capacitance: 1.5nF  (hidden comment: *)
Capacitor, Ceramic (MLCC), 1.5nF, ±10%, 100V, X7R, ±10%, SMD 0805; Manufacturer: KEMET; Manufacturer Part Number: C0805C152K1RAC7800
footprint CAP-0805 (0805 (2012M) Capacitor)
pins: 1, 2

## C0805C181J5RACAUTO
designator C?  Capacitance: 180pF  (hidden comment: *)
Capacitor, Ceramic (MLCC), 180pF, ±5%, 50V, X7R, ±5%, SMD 0805; Manufacturer: KEMET; Manufacturer Part Number: C0805C181J5RACAUTO
footprint CAP-0805 (0805 (2012M) Capacitor)
pins: 1, 2

## C0805C181MDRAC7800
designator C?  Capacitance: 180pF  (hidden comment: *)
Capacitor, Ceramic (MLCC), 180pF, ±20%, 1kV, X7R, ±20%, SMD 0805; Manufacturer: KEMET; Manufacturer Part Number: C0805C181MDRAC7800
footprint CAP-0805 (0805 (2012M) Capacitor)
pins: 1, 2

## C0805C200J5GACAUTO
designator C?  Capacitance: 20pF  (hidden comment: *)
Capacitor, Ceramic (MLCC), 20pF, ±5%, 50V, C0G, ±5%, SMD 0805; Manufacturer: KEMET; Manufacturer Part Number: C0805C200J5GACAUTO
footprint CAP-0805 (0805 (2012M) Capacitor)
pins: 1, 2

## C0805C201J5RACAUTO
designator C?  Capacitance: 200pF  (hidden comment: *)
Capacitor, Ceramic (MLCC), 200pF, ±5%, 50V, X7R, ±5%, SMD 0805; Manufacturer: KEMET; Manufacturer Part Number: C0805C201J5RACAUTO
footprint CAP-0805 (0805 (2012M) Capacitor)
pins: 1, 2

## C0805C220K5RACAUTO
designator C?  Capacitance: 22pF  (hidden comment: *)
Capacitor, Ceramic (MLCC), 22pF, ±10%, 50V, X7R, ±10%, SMD 0805; Manufacturer: KEMET; Manufacturer Part Number: C0805C220K5RACAUTO
footprint CAP-0805 (0805 (2012M) Capacitor)
pins: 1, 2

## C0805C221K5RACAUTO
designator C?  Capacitance: 220pF  (hidden comment: *)
Capacitor, Ceramic (MLCC), 220pF, ±10%, 50V, X7R, ±10%, SMD 0805; Manufacturer: KEMET; Manufacturer Part Number: C0805C221K5RACAUTO
footprint CAP-0805 (0805 (2012M) Capacitor)
pins: 1, 2

## C0805C222KDRACTU
designator C?  Capacitance: 2.2nF  (hidden comment: *)
Capacitor, Ceramic (MLCC), 2.2nF, ±10%, 1kV, X7R, ±10%, SMD 0805; Manufacturer: KEMET; Manufacturer Part Number: C0805C222KDRACTU
footprint CAP-0805 (0805 (2012M) Capacitor)
pins: 1, 2

## C0805C223K1RACAUTO
designator C?  Capacitance: 22nF  (hidden comment: *)
Capacitor, Ceramic (MLCC), 22nF, ±10%, 100V, X7R, ±10%, SMD 0805; Manufacturer: KEMET; Manufacturer Part Number: C0805C223K1RACAUTO
footprint CAP-0805 (0805 (2012M) Capacitor)
pins: 1, 2

## C0805C224K5RACAUTO
designator C?  Capacitance: 220nF  (hidden comment: *)
Capacitor, Ceramic (MLCC), 220nF, ±10%, 50V, X7R, ±10%, SMD 0805; Manufacturer: KEMET; Manufacturer Part Number: C0805C224K5RACAUTO
footprint CAP-0805 (0805 (2012M) Capacitor)
pins: 1, 2

## C0805C226M9PACTU
designator C?  Capacitance: 22uF  (hidden comment: *)
Capacitor, Ceramic (MLCC), 22uF, ±20%, 6.3V, X5R, ±20%, SMD 0805; Manufacturer: KEMET; Manufacturer Part Number: C0805C226M9PACTU
footprint CAP-0805 (0805 (2012M) Capacitor)
pins: 1, 2

## C0805C300K5RACAUTO
designator C?  Capacitance: 30pF  (hidden comment: *)
Capacitor, Ceramic (MLCC), 30pF, ±10%, 50V, X7R, ±10%, SMD 0805; Manufacturer: KEMET; Manufacturer Part Number: C0805C300K5RACAUTO
footprint CAP-0805 (0805 (2012M) Capacitor)
pins: 1, 2

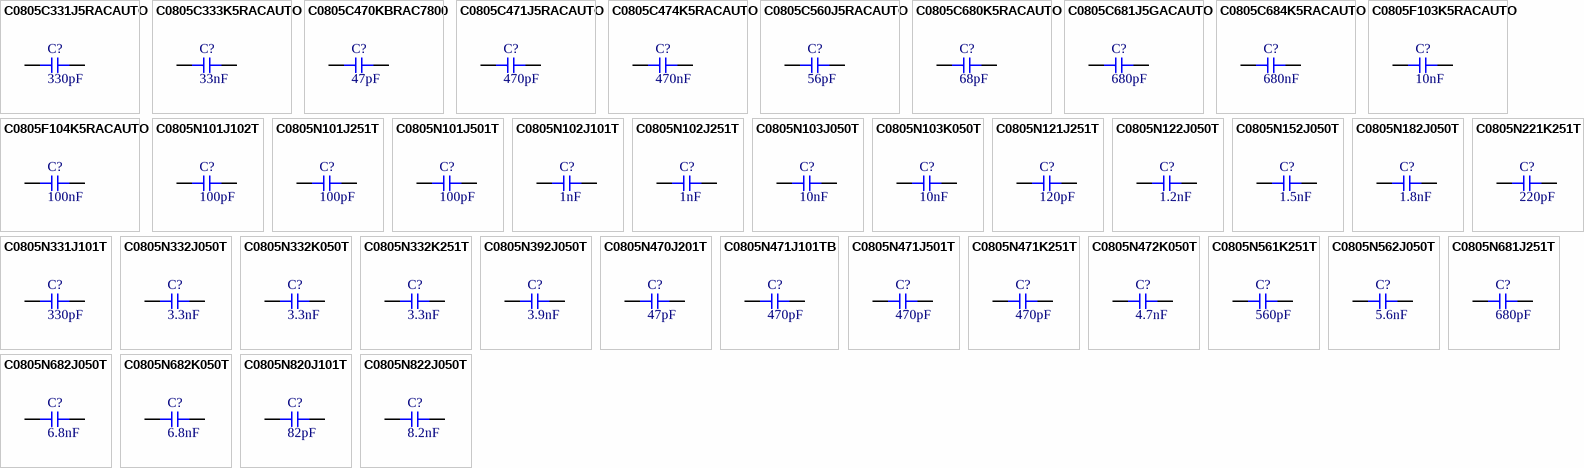
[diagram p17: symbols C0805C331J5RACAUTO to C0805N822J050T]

## C0805C331J5RACAUTO
designator C?  Capacitance: 330pF  (hidden comment: *)
Capacitor, Ceramic (MLCC), 330pF, ±5%, 50V, X7R, ±5%, SMD 0805; Manufacturer: KEMET; Manufacturer Part Number: C0805C331J5RACAUTO
footprint CAP-0805 (0805 (2012M) Capacitor)
pins: 1, 2

## C0805C333K5RACAUTO
designator C?  Capacitance: 33nF  (hidden comment: *)
Capacitor, Ceramic (MLCC), 33nF, ±10%, 50V, X7R, ±10%, SMD 0805; Manufacturer: KEMET; Manufacturer Part Number: C0805C333K5RACAUTO
footprint CAP-0805 (0805 (2012M) Capacitor)
pins: 1, 2

## C0805C470KBRAC7800
designator C?  Capacitance: 47pF  (hidden comment: *)
Capacitor, Ceramic (MLCC), 47pF, ±10%, 630V, X7R, ±10%, SMD 0805; Manufacturer: KEMET; Manufacturer Part Number: C0805C470KBRAC7800
footprint CAP-0805 (0805 (2012M) Capacitor)
pins: 1, 2

## C0805C471J5RACAUTO
designator C?  Capacitance: 470pF  (hidden comment: *)
Capacitor, Ceramic (MLCC), 470pF, ±5%, 50V, X7R, ±5%, SMD 0805; Manufacturer: KEMET; Manufacturer Part Number: C0805C471J5RACAUTO
footprint CAP-0805 (0805 (2012M) Capacitor)
pins: 1, 2

## C0805C474K5RACAUTO
designator C?  Capacitance: 470nF  (hidden comment: *)
Capacitor, Ceramic (MLCC), 470nF, ±10%, 50V, X7R, ±10%, SMD 0805; Manufacturer: KEMET; Manufacturer Part Number: C0805C474K5RACAUTO
footprint CAP-0805 (0805 (2012M) Capacitor)
pins: 1, 2

## C0805C560J5RACAUTO
designator C?  Capacitance: 56pF  (hidden comment: *)
Capacitor, Ceramic (MLCC), 56pF, ±5%, 50V, X7R, ±5%, SMD 0805; Manufacturer: KEMET; Manufacturer Part Number: C0805C560J5RACAUTO
footprint CAP-0805 (0805 (2012M) Capacitor)
pins: 1, 2

## C0805C680K5RACAUTO
designator C?  Capacitance: 68pF  (hidden comment: *)
Capacitor, Ceramic (MLCC), 68pF, ±10%, 50V, X7R, ±10%, SMD 0805; Manufacturer: KEMET; Manufacturer Part Number: C0805C680K5RACAUTO
footprint CAP-0805 (0805 (2012M) Capacitor)
pins: 1, 2

## C0805C681J5GACAUTO
designator C?  Capacitance: 680pF  (hidden comment: *)
Capacitor, Ceramic (MLCC), 680pF, ±5%, 50V, C0G, ±5%, SMD 0805; Manufacturer: KEMET; Manufacturer Part Number: C0805C681J5GACAUTO
footprint CAP-0805 (0805 (2012M) Capacitor)
pins: 1, 2

## C0805C684K5RACAUTO
designator C?  Capacitance: 680nF  (hidden comment: *)
Capacitor, Ceramic (MLCC), 680nF, ±10%, 50V, X7R, ±10%, SMD 0805; Manufacturer: KEMET; Manufacturer Part Number: C0805C684K5RACAUTO
footprint CAP-0805 (0805 (2012M) Capacitor)
pins: 1, 2

## C0805F103K5RACAUTO
designator C?  Capacitance: 10nF  (hidden comment: *)
Capacitor, Ceramic (MLCC), 10nF, ±10%, 50V, X7R, ±10%, SMD 0805; Manufacturer: KEMET; Manufacturer Part Number: C0805F103K5RACAUTO
footprint CAP-0805 (0805 (2012M) Capacitor)
pins: 1, 2

## C0805F104K5RACAUTO
designator C?  Capacitance: 100nF  (hidden comment: *)
Capacitor, Ceramic (MLCC), 100nF, ±10%, 50V, X7R, ±10%, SMD 0805; Manufacturer: KEMET; Manufacturer Part Number: C0805F104K5RACAUTO
footprint CAP-0805 (0805 (2012M) Capacitor)
pins: 1, 2

## C0805N101J102T
designator C?  Capacitance: 100pF  (hidden comment: *)
Capacitor, Ceramic (MLCC), 100pF, ±5%, 1kV, ±5%, SMD 0805; Manufacturer: IHHEC(HOLY STONE ENTERPRISE CO., LTD); Manufacturer Part Number: C0805N101J102T
footprint CAP-0805 (0805 (2012M) Capacitor)
pins: 1, 2

## C0805N101J251T
designator C?  Capacitance: 100pF  (hidden comment: *)
Capacitor, Ceramic (MLCC), 100pF, ±5%, 250V, NP0, ±5%, SMD 0805; Manufacturer: IHHEC(HOLY STONE ENTERPRISE CO., LTD); Manufacturer Part Number: C0805N101J251T
footprint CAP-0805 (0805 (2012M) Capacitor)
pins: 1, 2

## C0805N101J501T
designator C?  Capacitance: 100pF  (hidden comment: *)
Capacitor, Ceramic (MLCC), 100pF, ±5%, 500V, NP0, ±5%, SMD 0805; Manufacturer: IHHEC(HOLY STONE ENTERPRISE CO., LTD); Manufacturer Part Number: C0805N101J501T
footprint CAP-0805 (0805 (2012M) Capacitor)
pins: 1, 2

## C0805N102J101T
designator C?  Capacitance: 1nF  (hidden comment: *)
Capacitor, Ceramic (MLCC), 1nF, ±5%, 100V, NP0, ±5%, SMD 0805; Manufacturer: IHHEC(HOLY STONE ENTERPRISE CO., LTD); Manufacturer Part Number: C0805N102J101T
footprint CAP-0805 (0805 (2012M) Capacitor)
pins: 1, 2

## C0805N102J251T
designator C?  Capacitance: 1nF  (hidden comment: *)
Capacitor, Ceramic (MLCC), 1nF, ±5%, 250V, NP0, ±5%, SMD 0805; Manufacturer: IHHEC(HOLY STONE ENTERPRISE CO., LTD); Manufacturer Part Number: C0805N102J251T
footprint CAP-0805 (0805 (2012M) Capacitor)
pins: 1, 2

## C0805N103J050T
designator C?  Capacitance: 10nF  (hidden comment: *)
Capacitor, Ceramic (MLCC), 10nF, ±5%, 50V, NP0, ±5%, SMD 0805; Manufacturer: IHHEC(HOLY STONE ENTERPRISE CO., LTD); Manufacturer Part Number: C0805N103J050T
footprint CAP-0805 (0805 (2012M) Capacitor)
pins: 1, 2

## C0805N103K050T
designator C?  Capacitance: 10nF  (hidden comment: *)
Capacitor, Ceramic (MLCC), 10nF, ±10%, 50V, NP0, ±10%, SMD 0805; Manufacturer: IHHEC(HOLY STONE ENTERPRISE CO., LTD); Manufacturer Part Number: C0805N103K050T
footprint CAP-0805 (0805 (2012M) Capacitor)
pins: 1, 2

## C0805N121J251T
designator C?  Capacitance: 120pF  (hidden comment: *)
Capacitor, Ceramic (MLCC), 120pF, ±5%, 250V, NP0, ±5%, SMD 0805; Manufacturer: IHHEC(HOLY STONE ENTERPRISE CO., LTD); Manufacturer Part Number: C0805N121J251T
footprint CAP-0805 (0805 (2012M) Capacitor)
pins: 1, 2

## C0805N122J050T
designator C?  Capacitance: 1.2nF  (hidden comment: *)
Capacitor, Ceramic (MLCC), 1.2nF, ±5%, 50V, NP0, ±5%, SMD 0805; Manufacturer: IHHEC(HOLY STONE ENTERPRISE CO., LTD); Manufacturer Part Number: C0805N122J050T
footprint CAP-0805 (0805 (2012M) Capacitor)
pins: 1, 2

## C0805N152J050T
designator C?  Capacitance: 1.5nF  (hidden comment: *)
Capacitor, Ceramic (MLCC), 1.5nF, ±5%, 50V, NP0, ±5%, SMD 0805; Manufacturer: IHHEC(HOLY STONE ENTERPRISE CO., LTD); Manufacturer Part Number: C0805N152J050T
footprint CAP-0805 (0805 (2012M) Capacitor)
pins: 1, 2

## C0805N182J050T
designator C?  Capacitance: 1.8nF  (hidden comment: *)
Capacitor, Ceramic (MLCC), 1.8nF, ±5%, 50V, NP0, ±5%, SMD 0805; Manufacturer: IHHEC(HOLY STONE ENTERPRISE CO., LTD); Manufacturer Part Number: C0805N182J050T
footprint CAP-0805 (0805 (2012M) Capacitor)
pins: 1, 2

## C0805N221K251T
designator C?  Capacitance: 220pF  (hidden comment: *)
Capacitor, Ceramic (MLCC), 220pF, ±10%, 250V, NP0, ±10%, SMD 0805; Manufacturer: IHHEC(HOLY STONE ENTERPRISE CO., LTD); Manufacturer Part Number: C0805N221K251T
footprint CAP-0805 (0805 (2012M) Capacitor)
pins: 1, 2

## C0805N331J101T
designator C?  Capacitance: 330pF  (hidden comment: *)
Capacitor, Ceramic (MLCC), 330pF, ±5%, 100V, NP0, ±5%, SMD 0805; Manufacturer: IHHEC(HOLY STONE ENTERPRISE CO., LTD); Manufacturer Part Number: C0805N331J101T
footprint CAP-0805 (0805 (2012M) Capacitor)
pins: 1, 2

## C0805N332J050T
designator C?  Capacitance: 3.3nF  (hidden comment: *)
Capacitor, Ceramic (MLCC), 3.3nF, ±5%, 50V, NP0, ±5%, SMD 0805; Manufacturer: IHHEC(HOLY STONE ENTERPRISE CO., LTD); Manufacturer Part Number: C0805N332J050T
footprint CAP-0805 (0805 (2012M) Capacitor)
pins: 1, 2

## C0805N332K050T
designator C?  Capacitance: 3.3nF  (hidden comment: *)
Capacitor, Ceramic (MLCC), 3.3nF, ±10%, 50V, NP0, ±10%, SMD 0805; Manufacturer: IHHEC(HOLY STONE ENTERPRISE CO., LTD); Manufacturer Part Number: C0805N332K050T
footprint CAP-0805 (0805 (2012M) Capacitor)
pins: 1, 2

## C0805N332K251T
designator C?  Capacitance: 3.3nF  (hidden comment: *)
Capacitor, Ceramic (MLCC), 3.3nF, ±10%, 250V, NP0, ±10%, SMD 0805; Manufacturer: IHHEC(HOLY STONE ENTERPRISE CO., LTD); Manufacturer Part Number: C0805N332K251T
footprint CAP-0805 (0805 (2012M) Capacitor)
pins: 1, 2

## C0805N392J050T
designator C?  Capacitance: 3.9nF  (hidden comment: *)
Capacitor, Ceramic (MLCC), 3.9nF, ±5%, 50V, NP0, ±5%, SMD 0805; Manufacturer: IHHEC(HOLY STONE ENTERPRISE CO., LTD); Manufacturer Part Number: C0805N392J050T
footprint CAP-0805 (0805 (2012M) Capacitor)
pins: 1, 2

## C0805N470J201T
designator C?  Capacitance: 47pF  (hidden comment: *)
Capacitor, Ceramic (MLCC), 47pF, ±5%, 200V, NP0, ±5%, SMD 0805; Manufacturer: IHHEC(HOLY STONE ENTERPRISE CO., LTD); Manufacturer Part Number: C0805N470J201T
footprint CAP-0805 (0805 (2012M) Capacitor)
pins: 1, 2

## C0805N471J101TB
designator C?  Capacitance: 470pF  (hidden comment: *)
Capacitor, Ceramic (MLCC), 470pF, ±5%, 100V, NP0, ±5%, SMD 0805; Manufacturer: IHHEC(HOLY STONE ENTERPRISE CO., LTD); Manufacturer Part Number: C0805N471J101TB
footprint CAP-0805 (0805 (2012M) Capacitor)
pins: 1, 2

## C0805N471J501T
designator C?  Capacitance: 470pF  (hidden comment: *)
Capacitor, Ceramic (MLCC), 470pF, ±5%, 500V, NP0, ±5%, SMD 0805; Manufacturer: IHHEC(HOLY STONE ENTERPRISE CO., LTD); Manufacturer Part Number: C0805N471J501T
footprint CAP-0805 (0805 (2012M) Capacitor)
pins: 1, 2

## C0805N471K251T
designator C?  Capacitance: 470pF  (hidden comment: *)
Capacitor, Ceramic (MLCC), 470pF, ±10%, 250V, NP0, ±10%, SMD 0805; Manufacturer: IHHEC(HOLY STONE ENTERPRISE CO., LTD); Manufacturer Part Number: C0805N471K251T
footprint CAP-0805 (0805 (2012M) Capacitor)
pins: 1, 2

## C0805N472K050T
designator C?  Capacitance: 4.7nF  (hidden comment: *)
Capacitor, Ceramic (MLCC), 4.7nF, ±10%, 50V, NP0, ±10%, SMD 0805; Manufacturer: IHHEC(HOLY STONE ENTERPRISE CO., LTD); Manufacturer Part Number: C0805N472K050T
footprint CAP-0805 (0805 (2012M) Capacitor)
pins: 1, 2

## C0805N561K251T
designator C?  Capacitance: 560pF  (hidden comment: *)
Capacitor, Ceramic (MLCC), 560pF, ±10%, 250V, NP0, ±10%, SMD 0805; Manufacturer: IHHEC(HOLY STONE ENTERPRISE CO., LTD); Manufacturer Part Number: C0805N561K251T
footprint CAP-0805 (0805 (2012M) Capacitor)
pins: 1, 2

## C0805N562J050T
designator C?  Capacitance: 5.6nF  (hidden comment: *)
Capacitor, Ceramic (MLCC), 5.6nF, ±5%, 50V, NP0, ±5%, SMD 0805; Manufacturer: IHHEC(HOLY STONE ENTERPRISE CO., LTD); Manufacturer Part Number: C0805N562J050T
footprint CAP-0805 (0805 (2012M) Capacitor)
pins: 1, 2

## C0805N681J251T
designator C?  Capacitance: 680pF  (hidden comment: *)
Capacitor, Ceramic (MLCC), 680pF, ±5%, 250V, NP0, ±5%, SMD 0805; Manufacturer: IHHEC(HOLY STONE ENTERPRISE CO., LTD); Manufacturer Part Number: C0805N681J251T
footprint CAP-0805 (0805 (2012M) Capacitor)
pins: 1, 2

## C0805N682J050T
designator C?  Capacitance: 6.8nF  (hidden comment: *)
Capacitor, Ceramic (MLCC), 6.8nF, ±5%, 50V, NP0, ±5%, SMD 0805; Manufacturer: IHHEC(HOLY STONE ENTERPRISE CO., LTD); Manufacturer Part Number: C0805N682J050T
footprint CAP-0805 (0805 (2012M) Capacitor)
pins: 1, 2

## C0805N682K050T
designator C?  Capacitance: 6.8nF  (hidden comment: *)
Capacitor, Ceramic (MLCC), 6.8nF, ±10%, 50V, NP0, ±10%, SMD 0805; Manufacturer: IHHEC(HOLY STONE ENTERPRISE CO., LTD); Manufacturer Part Number: C0805N682K050T
footprint CAP-0805 (0805 (2012M) Capacitor)
pins: 1, 2

## C0805N820J101T
designator C?  Capacitance: 82pF  (hidden comment: *)
Capacitor, Ceramic (MLCC), 82pF, ±5%, 100V, NP0, ±5%, SMD 0805; Manufacturer: IHHEC(HOLY STONE ENTERPRISE CO., LTD); Manufacturer Part Number: C0805N820J101T
footprint CAP-0805 (0805 (2012M) Capacitor)
pins: 1, 2

## C0805N822J050T
designator C?  Capacitance: 8.2nF  (hidden comment: *)
Capacitor, Ceramic (MLCC), 8.2nF, ±5%, 50V, NP0, ±5%, SMD 0805; Manufacturer: IHHEC(HOLY STONE ENTERPRISE CO., LTD); Manufacturer Part Number: C0805N822J050T
footprint CAP-0805 (0805 (2012M) Capacitor)
pins: 1, 2

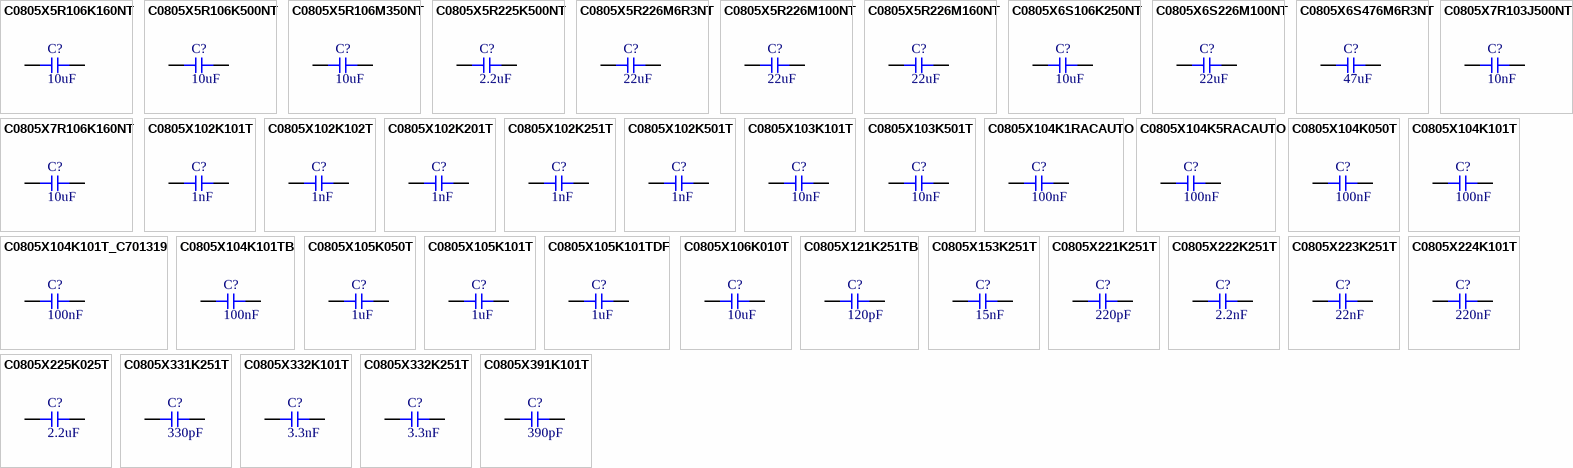
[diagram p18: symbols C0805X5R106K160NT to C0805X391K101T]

## C0805X5R106K160NT
designator C?  Capacitance: 10uF  (hidden comment: *)
Capacitor, Ceramic (MLCC), 10uF, ±10%, 16V, X5R, ±10%, SMD 0805; Manufacturer: SANYEAR; Manufacturer Part Number: C0805X5R106K160NT
footprint CAP-0805 (0805 (2012M) Capacitor)
pins: 1, 2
